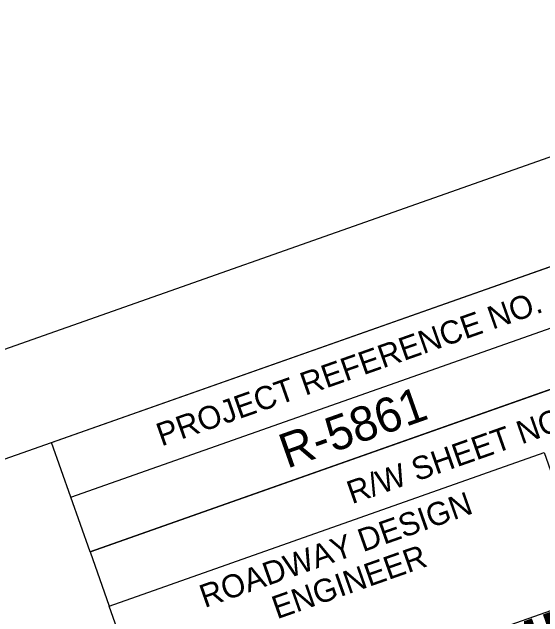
# Model space of a CAD drawing. Extents: x 473817 to 475769, y 501102 to 502694.
# Drawn here: x 475199.4 to 475314.5, y 502563 to 502694.2 of the extents above; entities that cross this region are included whole.
import ezdxf

# ---------------------------------------------------------------- set-up
doc = ezdxf.new("R2010")
doc.units = 0
for name, color, linetype in [('Sheet Data Field CELL', 7, 'Continuous'), ('Sheet Plan CELL', 7, 'Continuous'), ('Sheet Plot Border Outside CELL', 7, 'Continuous'), ('Sheet Sticker Incomplete CELL', 7, 'Continuous')]:
    doc.layers.add(name, color=color, linetype=linetype)

msp = doc.modelspace()

# ---------------------------------------------------------------- linework, layer by layer
at = {"layer": 'Sheet Plan CELL'}
for p, q in [((475212.12, 502588.95), (475400.78, 502655.46)), ((475216.3, 502577.13), (475404.94, 502643.68)), ((475216.3, 502577.13), (475404.94, 502643.68)), ((475216.3, 502577.13), (475220.45, 502565.36))]:
    msp.add_line(p, q, dxfattribs=at)
for points in [[(475396.65, 502667.31), (473981.98, 502168.49), (474331.14, 501178.25), (475745.79, 501677.06)], [(475207.95, 502600.79), (475396.65, 502667.31), (475404.94, 502643.68), (475216.3, 502577.13)], [(475220.45, 502565.36), (475314.81, 502598.63), (475352.22, 502492.52), (475257.87, 502459.27)]]:
    msp.add_lwpolyline(points, close=True, dxfattribs=at)
at = {"layer": 'Sheet Plot Border Outside CELL'}
msp.add_lwpolyline([(474181.62, 501101.65), (475769.31, 501661.48), (475405.18, 502694.17), (473817.49, 502134.34)], close=True, dxfattribs=at)
at = {"layer": 'Sheet Sticker Incomplete CELL'}
msp.add_lwpolyline([(475264.19, 502521.14), (475256.38, 502543.3), (475395.01, 502592.18), (475402.83, 502570.02)], close=True, dxfattribs=at)

# ---------------------------------------------------------------- texts
at = {"layer": 'Sheet Data Field CELL'}
msp.add_text('R-5861', height=7.5, rotation=19.423, dxfattribs=at).set_placement((475259.01, 502595.12))
at = {"layer": 'Sheet Plan CELL'}
for s, height, p in [('PROJECT REFERENCE NO.', 5.0001, (475231.79, 502599.95)), ('R/W SHEET NO.', 5.0001, (475273.11, 502587.42)), ('ROADWAY DESIGN', 5.0001, (475241.15, 502564.91)), ('ENGINEER', 5, (475256.85, 502562.46))]:
    msp.add_text(s, height=height, rotation=19.423, dxfattribs=at).set_placement(p)
at = {"layer": 'Sheet Sticker Incomplete CELL'}
for s, height, p in [('INCOMPLETE PLANS', 11.52, (475268.74, 502535.15)), ('DO NOT USE FOR R/W ACQUISITION', 5.76, (475274.12, 502529.67))]:
    msp.add_text(s, height=height, rotation=19.423, dxfattribs=at).set_placement(p)

doc.saveas('drawing.dxf')
